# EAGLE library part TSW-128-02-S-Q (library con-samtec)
THROUGH-HOLE .025" SQ POST HEADER Source: Samtec TSW.pdf
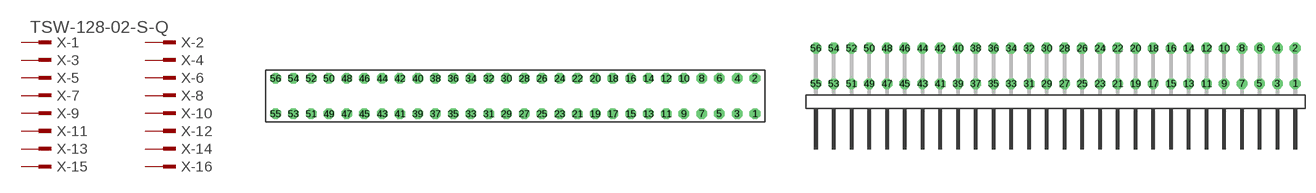
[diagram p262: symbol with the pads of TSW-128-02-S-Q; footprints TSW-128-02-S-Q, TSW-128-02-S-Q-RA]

Designator prefix X; gates -1=MPINV -2=MPIN -3=MPIN -4=MPIN -5=MPIN -6=MPIN -7=MPIN -8=MPIN -9=MPIN -10=MPIN -11=MPIN -12=MPIN -13=MPIN -14=MPIN -15=MPIN -16=MPIN -17=MPIN -18=MPIN -19=MPIN -20=MPIN -21=MPIN -22=MPIN -23=MPIN -24=MPIN -25=MPIN -26=MPIN -27=MPIN -28=MPIN -29=MPIN -30=MPIN -31=MPIN -32=MPIN -33=MPIN -34=MPIN -35=MPIN -36=MPIN -37=MPIN -38=MPIN -39=MPIN -40=MPIN -41=MPIN -42=MPIN -43=MPIN -44=MPIN -45=MPIN -46=MPIN -47=MPIN -48=MPIN -49=MPIN -50=MPIN -51=MPIN -52=MPIN -53=MPIN -54=MPIN -55=MPIN -56=MPIN

## TSW-128-02-S-Q (OC_FARNELL: unknown; OC_NEWARK: unknown)  [TSW-128-02-S-Q]
1  -1:1  pas
2  -2:1  pas
3  -3:1  pas
4  -4:1  pas
5  -5:1  pas
6  -6:1  pas
7  -7:1  pas
8  -8:1  pas
9  -9:1  pas
10  -10:1  pas
11  -11:1  pas
12  -12:1  pas
13  -13:1  pas
14  -14:1  pas
15  -15:1  pas
16  -16:1  pas
17  -17:1  pas
18  -18:1  pas
19  -19:1  pas
20  -20:1  pas
21  -21:1  pas
22  -22:1  pas
23  -23:1  pas
24  -24:1  pas
25  -25:1  pas
26  -26:1  pas
27  -27:1  pas
28  -28:1  pas
29  -29:1  pas
30  -30:1  pas
31  -31:1  pas
32  -32:1  pas
33  -33:1  pas
34  -34:1  pas
35  -35:1  pas
36  -36:1  pas
37  -37:1  pas
38  -38:1  pas
39  -39:1  pas
40  -40:1  pas
41  -41:1  pas
42  -42:1  pas
43  -43:1  pas
44  -44:1  pas
45  -45:1  pas
46  -46:1  pas
47  -47:1  pas
48  -48:1  pas
49  -49:1  pas
50  -50:1  pas
51  -51:1  pas
52  -52:1  pas
53  -53:1  pas
54  -54:1  pas
55  -55:1  pas
56  -56:1  pas

## TSW-128-02-S-Q-RA (OC_FARNELL: unknown; OC_NEWARK: unknown)  [TSW-128-02-S-Q-RA]
Pads as for TSW-128-02-S-Q

## Footprint TSW-128-02-S-Q (pad centres in mm)
THROUGH-HOLE .025" SQ POST HEADER Source: Samtec TSW.pdf
drill 1 pad 1.5 octagon: 1 34.29,-2.54; 2 34.29,2.54; 3 31.75,-2.54; 4 31.75,2.54; 5 29.21,-2.54; 6 29.21,2.54; 7 26.67,-2.54; 8 26.67,2.54; 9 24.13,-2.54; 10 24.13,2.54; 11 21.59,-2.54; 12 21.59,2.54; 13 19.05,-2.54; 14 19.05,2.54; 15 16.51,-2.54; 16 16.51,2.54; 17 13.97,-2.54; 18 13.97,2.54; 19 11.43,-2.54; 20 11.43,2.54; 21 8.89,-2.54; 22 8.89,2.54; 23 6.35,-2.54; 24 6.35,2.54; 25 3.81,-2.54; 26 3.81,2.54; 27 1.27,-2.54; 28 1.27,2.54; 29 -1.27,-2.54; 30 -1.27,2.54; 31 -3.81,-2.54; 32 -3.81,2.54; 33 -6.35,-2.54; 34 -6.35,2.54; 35 -8.89,-2.54; 36 -8.89,2.54; 37 -11.43,-2.54; 38 -11.43,2.54; 39 -13.97,-2.54; 40 -13.97,2.54; 41 -16.51,-2.54; 42 -16.51,2.54; 43 -19.05,-2.54; 44 -19.05,2.54; 45 -21.59,-2.54; 46 -21.59,2.54; 47 -24.13,-2.54; 48 -24.13,2.54; 49 -26.67,-2.54; 50 -26.67,2.54; 51 -29.21,-2.54; 52 -29.21,2.54; 53 -31.75,-2.54; 54 -31.75,2.54; 55 -34.29,-2.54; 56 -34.29,2.54

## Footprint TSW-128-02-S-Q-RA (pad centres in mm)
THROUGH-HOLE .025" SQ POST HEADER Source: Samtec TSW.pdf
drill 1 pad 1.5 octagon: 1 34.29,1.524; 2 34.29,6.604; 3 31.75,1.524; 4 31.75,6.604; 5 29.21,1.524; 6 29.21,6.604; 7 26.67,1.524; 8 26.67,6.604; 9 24.13,1.524; 10 24.13,6.604; 11 21.59,1.524; 12 21.59,6.604; 13 19.05,1.524; 14 19.05,6.604; 15 16.51,1.524; 16 16.51,6.604; 17 13.97,1.524; 18 13.97,6.604; 19 11.43,1.524; 20 11.43,6.604; 21 8.89,1.524; 22 8.89,6.604; 23 6.35,1.524; 24 6.35,6.604; 25 3.81,1.524; 26 3.81,6.604; 27 1.27,1.524; 28 1.27,6.604; 29 -1.27,1.524; 30 -1.27,6.604; 31 -3.81,1.524; 32 -3.81,6.604; 33 -6.35,1.524; 34 -6.35,6.604; 35 -8.89,1.524; 36 -8.89,6.604; 37 -11.43,1.524; 38 -11.43,6.604; 39 -13.97,1.524; 40 -13.97,6.604; 41 -16.51,1.524; 42 -16.51,6.604; 43 -19.05,1.524; 44 -19.05,6.604; 45 -21.59,1.524; 46 -21.59,6.604; 47 -24.13,1.524; 48 -24.13,6.604; 49 -26.67,1.524; 50 -26.67,6.604; 51 -29.21,1.524; 52 -29.21,6.604; 53 -31.75,1.524; 54 -31.75,6.604; 55 -34.29,1.524; 56 -34.29,6.604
